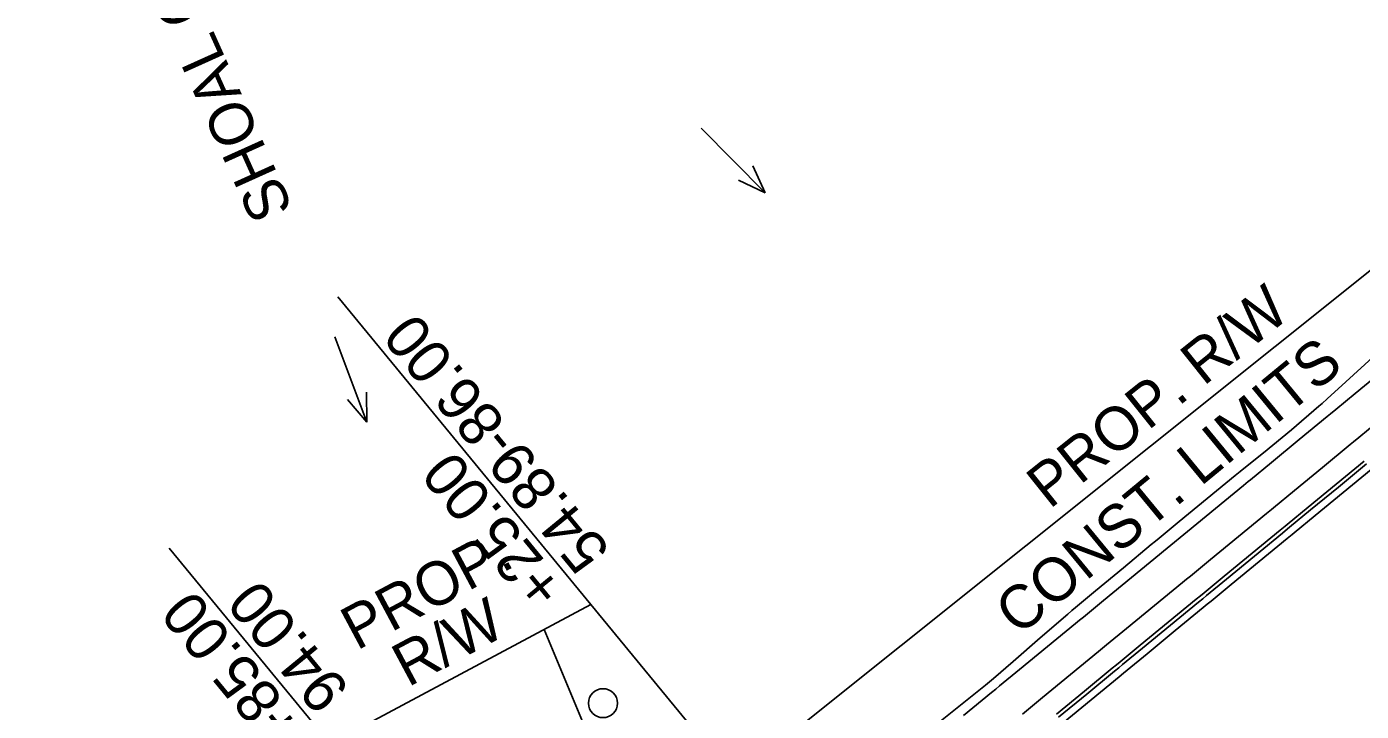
# Model space of a CAD drawing. Extents: x 1147550 to 1149124, y 2017436 to 2018779.
# Drawn here: x 1147550.1 to 1147734.3, y 2017613.3 to 2017707.7 of the extents above; entities that cross this region are included whole.
import ezdxf

# ---------------------------------------------------------------- set-up
doc = ezdxf.new("R2010")
doc.units = 0
for name, color, linetype in [('S_ELECTRIC_UTILITIES', 7, 'Continuous'), ('S_HEADWALL', 7, 'Continuous'), ('S_MAILBOX', 7, 'Continuous'), ('S_SECONDARY_CTL', 7, 'Continuous'), ('S_STORM_SEWER', 7, 'Continuous'), ('S_TANK', 7, 'Continuous'), ('S_TELEPHONE_UTILITIES', 7, 'Continuous'), ('S_TELEPHONE_UTILITIES_ANNOT', 7, 'Continuous')]:
    doc.layers.add(name, color=color, linetype=linetype)

msp = doc.modelspace()

# ---------------------------------------------------------------- linework, layer by layer
at = {"layer": 'S_ELECTRIC_UTILITIES'}
for points in [[(1147627.98, 2017627.98), (1147593.05, 2017670.46)], [(1147592.01, 2017608.75), (1147569.78, 2017635.79)]]:
    msp.add_lwpolyline(points, dxfattribs=at)
at = {"layer": 'S_HEADWALL'}
msp.add_line((1147621.53, 2017624.53), (1147627.73, 2017609.62), dxfattribs=at)
at = {"layer": 'S_MAILBOX'}
msp.add_line((1147627.98, 2017627.98), (1147647.75, 2017603.95), dxfattribs=at)
for points in [[(1147550.1, 2017525.89), (1147894.72, 2017801.4), (1147903.55, 2017831.14), (1148035.64, 2017933.4), (1148261.5, 2018084.85), (1148285.74, 2018084.65), (1148479.1, 2018223.18), (1148835.76, 2018573.62)], [(1147596.97, 2017563.36), (1147592.01, 2017608.75), (1147627.98, 2017627.98)]]:
    msp.add_lwpolyline(points, dxfattribs=at)
at = {"layer": 'S_SECONDARY_CTL'}
msp.add_lwpolyline([(1147674.64, 2017610.61), (1147678.54, 2017613.74), (1147682.43, 2017616.88), (1147683, 2017617.34), (1147683.53, 2017617.78), (1147686.24, 2017620.12), (1147690.01, 2017623.4), (1147693.79, 2017626.68), (1147694.35, 2017627.16), (1147694.86, 2017627.6), (1147697.63, 2017629.89), (1147701.48, 2017633.08), (1147705.33, 2017636.27), (1147705.9, 2017636.73), (1147706.41, 2017637.16), (1147709.18, 2017639.45), (1147713.04, 2017642.63), (1147716.92, 2017645.79), (1147717.6, 2017646.34), (1147717.89, 2017646.58), (1147720.8, 2017648.94), (1147724.68, 2017652.1), (1147728.46, 2017655.37), (1147728.9, 2017655.74), (1147729.6, 2017656.38), (1147732.17, 2017658.73), (1147735.88, 2017662.1)], dxfattribs=at)
at = {"layer": 'S_TANK'}
for p, q in [((1147643.21, 2017693.73), (1147652.05, 2017684.8)), ((1147652.05, 2017684.8), (1147650.34, 2017688.52)), ((1147652.05, 2017684.8), (1147648.35, 2017686.55)), ((1147592.63, 2017664.95), (1147597.05, 2017653.18)), ((1147597.05, 2017653.18), (1147597.01, 2017657.28)), ((1147597.05, 2017653.18), (1147594.39, 2017656.29))]:
    msp.add_line(p, q, dxfattribs=at)
at = {"layer": 'S_TELEPHONE_UTILITIES'}
for points in [[(1147679.42, 2017612.67), (1147683.28, 2017615.84), (1147683.85, 2017616.31), (1147684.38, 2017616.75), (1147687.14, 2017619.02), (1147691.01, 2017622.2), (1147694.87, 2017625.37), (1147695.44, 2017625.84), (1147695.96, 2017626.27), (1147698.73, 2017628.55), (1147702.59, 2017631.72), (1147706.45, 2017634.9), (1147707.02, 2017635.37), (1147707.54, 2017635.79), (1147710.32, 2017638.08), (1147714.18, 2017641.25), (1147718.04, 2017644.43), (1147718.72, 2017644.99), (1147719.01, 2017645.22), (1147721.9, 2017647.6), (1147725.76, 2017650.78), (1147729.62, 2017653.95), (1147730.07, 2017654.32), (1147730.8, 2017654.92), (1147733.49, 2017657.13), (1147737.35, 2017660.31)], [(1147687.56, 2017612.88), (1147690.32, 2017615.16), (1147694.18, 2017618.33), (1147698.04, 2017621.51), (1147698.61, 2017621.98), (1147699.13, 2017622.41), (1147701.91, 2017624.69), (1147705.77, 2017627.86), (1147709.63, 2017631.04), (1147710.2, 2017631.5), (1147710.72, 2017631.93), (1147713.49, 2017634.21), (1147717.35, 2017637.39), (1147721.22, 2017640.57), (1147721.9, 2017641.12), (1147722.18, 2017641.36), (1147725.08, 2017643.74), (1147728.94, 2017646.92), (1147732.8, 2017650.09), (1147733.25, 2017650.46), (1147733.98, 2017651.06), (1147736.66, 2017653.27)], [(1147692.23, 2017612.84), (1147696.09, 2017616.02), (1147699.95, 2017619.19), (1147700.52, 2017619.66), (1147701.04, 2017620.09), (1147703.81, 2017622.37), (1147707.67, 2017625.54), (1147711.54, 2017628.72), (1147712.1, 2017629.19), (1147712.62, 2017629.61), (1147715.4, 2017631.9), (1147719.26, 2017635.07), (1147723.12, 2017638.25), (1147723.8, 2017638.81), (1147724.09, 2017639.04), (1147726.98, 2017641.42), (1147730.84, 2017644.6), (1147734.71, 2017647.78)], [(1147692.54, 2017612.45), (1147696.41, 2017615.63), (1147700.27, 2017618.81), (1147700.84, 2017619.27), (1147701.36, 2017619.7), (1147704.13, 2017621.98), (1147707.99, 2017625.16), (1147711.85, 2017628.33), (1147712.42, 2017628.8), (1147712.94, 2017629.23), (1147715.71, 2017631.51), (1147719.58, 2017634.69), (1147723.44, 2017637.86), (1147724.12, 2017638.42), (1147724.41, 2017638.66), (1147727.3, 2017641.04), (1147731.16, 2017644.21), (1147735.02, 2017647.39)], [(1147693.18, 2017611.68), (1147697.04, 2017614.86), (1147700.9, 2017618.03), (1147701.47, 2017618.5), (1147701.99, 2017618.93), (1147704.76, 2017621.21), (1147708.63, 2017624.39), (1147712.49, 2017627.56), (1147713.05, 2017628.03), (1147713.57, 2017628.46), (1147716.35, 2017630.74), (1147720.21, 2017633.91), (1147724.07, 2017637.09), (1147724.75, 2017637.65), (1147725.04, 2017637.88), (1147727.94, 2017640.27), (1147731.8, 2017643.44), (1147735.66, 2017646.62)]]:
    msp.add_lwpolyline(points, dxfattribs=at)
at = {"layer": 'S_TELEPHONE_UTILITIES_ANNOT'}
msp.add_circle((1147629.65, 2017614.38), 2, dxfattribs=at)

# ---------------------------------------------------------------- texts
at = {"layer": 'S_ELECTRIC_UTILITIES'}
for s, p in [('54.89-86.00', (1147630.85, 2017635.52)), ('+25.00', (1147624.67, 2017630.44)), ('94.00', (1147594.87, 2017616.29)), ('+85.00', (1147588.7, 2017611.21))]:
    msp.add_text(s, height=6, rotation=129.4333, dxfattribs=at).set_placement(p)
at = {"layer": 'S_MAILBOX'}
for s, rotation, p in [('PROP. R/W', 38.6406, (1147691.29, 2017641.07)), ('PROP.', 28.1234, (1147595.66, 2017621.59)), ('R/W', 28.1234, (1147602.73, 2017616.53))]:
    msp.add_text(s, height=6, rotation=rotation, dxfattribs=at).set_placement(p)
at = {"layer": 'S_SECONDARY_CTL'}
msp.add_text('CONST. LIMITS', height=6, rotation=39.4813, dxfattribs=at).set_placement((1147687.01, 2017623.52))
at = {"layer": 'S_STORM_SEWER'}
msp.add_text('SHOAL CREEK DR.', height=6, rotation=114.2558, dxfattribs=at).set_placement((1147586.95, 2017682.56))

doc.saveas('drawing.dxf')
